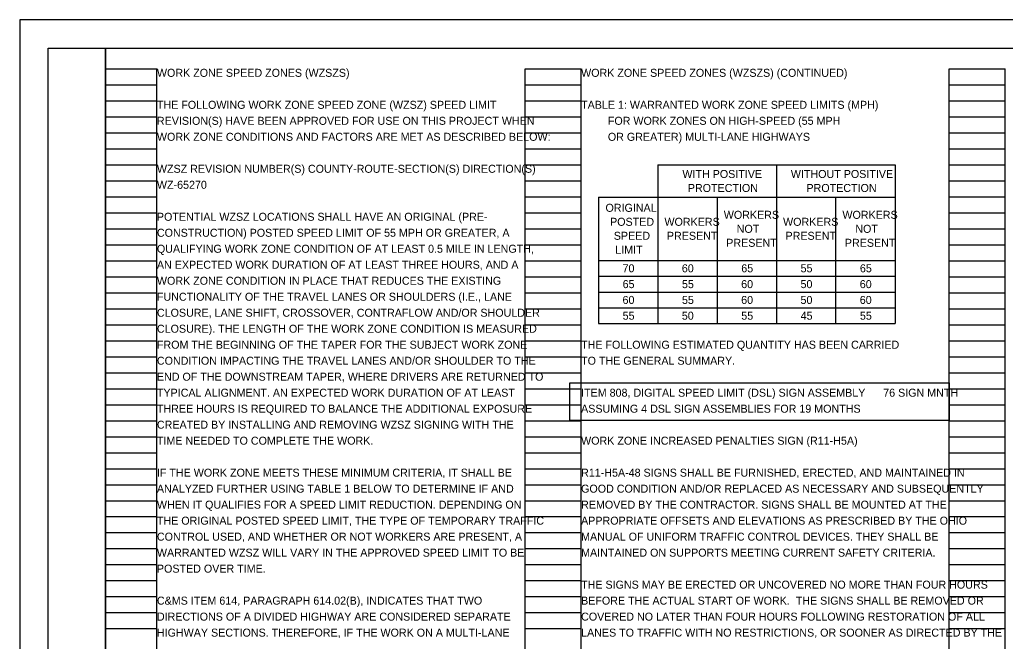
# Model space of a CAD drawing. Extents: x -19 to 34, y 0 to 22.
# Drawn here: x 0 to 17.24, y 11.12 to 22 of the extents above; entities that cross this region are included whole.
import ezdxf

# ---------------------------------------------------------------- set-up
doc = ezdxf.new("R2010")
doc.units = 0
for name, color, linetype in [('SC_Scratch1', 7, 'Continuous'), ('SH_Border', 7, 'Continuous'), ('SH_Cut_Line', 7, 'Continuous'), ('SH_Data', 7, 'Continuous'), ('SH_Text', 7, 'Continuous')]:
    doc.layers.add(name, color=color, linetype=linetype)

msp = doc.modelspace()

# ---------------------------------------------------------------- linework, layer by layer
at = {"layer": 'SC_Scratch1'}
msp.add_lwpolyline([(9.625, 15.64), (16.259, 15.64), (16.259, 14.983), (9.625, 14.983)], close=True, dxfattribs=at)
at = {"layer": 'SH_Border'}
for points in [[(0.5, 21.5), (1.5, 21.5), (1.5, 0.5), (0.5, 0.5)], [(1.5, 21.5), (33.5, 21.5), (33.5, 0.5), (1.5, 0.5)]]:
    msp.add_lwpolyline(points, close=True, dxfattribs=at)
at = {"layer": 'SH_Cut_Line'}
msp.add_lwpolyline([(0, 0), (34, 0), (34, 22), (0, 22)], close=True, dxfattribs=at)
at = {"layer": 'SH_Data'}
for p, q in [((1.5, 0.98), (1.5, 21.14)), ((1.5, 21.14), (2.4, 21.14)), ((2.4, 0.98), (2.4, 21.14)), ((8.84, 0.98), (8.84, 21.14)), ((8.84, 21.14), (9.82, 21.14)), ((9.82, 0.98), (9.82, 21.14)), ((16.26, 0.98), (16.26, 21.14)), ((16.26, 21.14), (17.24, 21.14)), ((17.24, 0.98), (17.24, 21.14)), ((1.5, 20.86), (2.4, 20.86)), ((8.84, 20.86), (9.82, 20.86)), ((16.26, 20.86), (17.24, 20.86)), ((1.5, 20.58), (2.4, 20.58)), ((8.84, 20.58), (9.82, 20.58)), ((16.26, 20.58), (17.24, 20.58)), ((1.5, 20.3), (2.4, 20.3)), ((8.84, 20.3), (9.82, 20.3)), ((16.26, 20.3), (17.24, 20.3)), ((1.5, 20.02), (2.4, 20.02)), ((8.84, 20.02), (9.82, 20.02)), ((16.26, 20.02), (17.24, 20.02)), ((1.5, 19.74), (2.4, 19.74)), ((8.84, 19.74), (9.82, 19.74)), ((16.26, 19.74), (17.24, 19.74)), ((1.5, 19.46), (2.4, 19.46)), ((8.84, 19.46), (9.82, 19.46)), ((16.26, 19.46), (17.24, 19.46)), ((1.5, 19.18), (2.4, 19.18)), ((8.84, 19.18), (9.82, 19.18)), ((16.26, 19.18), (17.24, 19.18)), ((1.5, 18.9), (2.4, 18.9)), ((8.84, 18.9), (9.82, 18.9)), ((16.26, 18.9), (17.24, 18.9)), ((1.5, 18.62), (2.4, 18.62)), ((8.84, 18.62), (9.82, 18.62)), ((16.26, 18.62), (17.24, 18.62)), ((1.5, 18.34), (2.4, 18.34)), ((8.84, 18.34), (9.82, 18.34)), ((16.26, 18.34), (17.24, 18.34)), ((1.5, 18.06), (2.4, 18.06)), ((8.84, 18.06), (9.82, 18.06)), ((16.26, 18.06), (17.24, 18.06)), ((1.5, 17.78), (2.4, 17.78)), ((8.84, 17.78), (9.82, 17.78)), ((16.26, 17.78), (17.24, 17.78)), ((1.5, 17.5), (2.4, 17.5)), ((8.84, 17.5), (9.82, 17.5)), ((16.26, 17.5), (17.24, 17.5)), ((1.5, 17.22), (2.4, 17.22)), ((8.84, 17.22), (9.82, 17.22)), ((16.26, 17.22), (17.24, 17.22)), ((1.5, 16.94), (2.4, 16.94)), ((8.84, 16.94), (9.82, 16.94)), ((16.26, 16.94), (17.24, 16.94)), ((1.5, 16.66), (2.4, 16.66)), ((8.84, 16.66), (9.82, 16.66)), ((16.26, 16.66), (17.24, 16.66)), ((1.5, 16.38), (2.4, 16.38)), ((8.84, 16.38), (9.82, 16.38)), ((16.26, 16.38), (17.24, 16.38)), ((1.5, 16.1), (2.4, 16.1)), ((8.84, 16.1), (9.82, 16.1)), ((16.26, 16.1), (17.24, 16.1)), ((1.5, 15.82), (2.4, 15.82)), ((8.84, 15.82), (9.82, 15.82)), ((16.26, 15.82), (17.24, 15.82)), ((1.5, 15.54), (2.4, 15.54)), ((8.84, 15.54), (9.82, 15.54)), ((16.26, 15.54), (17.24, 15.54)), ((1.5, 15.26), (2.4, 15.26)), ((8.84, 15.26), (9.82, 15.26)), ((16.26, 15.26), (17.24, 15.26)), ((1.5, 14.98), (2.4, 14.98)), ((8.84, 14.98), (9.82, 14.98)), ((16.26, 14.98), (17.24, 14.98)), ((1.5, 14.7), (2.4, 14.7)), ((8.84, 14.7), (9.82, 14.7)), ((16.26, 14.7), (17.24, 14.7)), ((1.5, 14.42), (2.4, 14.42)), ((8.84, 14.42), (9.82, 14.42)), ((16.26, 14.42), (17.24, 14.42)), ((1.5, 14.14), (2.4, 14.14)), ((8.84, 14.14), (9.82, 14.14)), ((16.26, 14.14), (17.24, 14.14)), ((1.5, 13.86), (2.4, 13.86)), ((8.84, 13.86), (9.82, 13.86)), ((16.26, 13.86), (17.24, 13.86)), ((1.5, 13.58), (2.4, 13.58)), ((8.84, 13.58), (9.82, 13.58)), ((16.26, 13.58), (17.24, 13.58)), ((1.5, 13.3), (2.4, 13.3)), ((8.84, 13.3), (9.82, 13.3)), ((16.26, 13.3), (17.24, 13.3)), ((1.5, 13.02), (2.4, 13.02)), ((8.84, 13.02), (9.82, 13.02)), ((16.26, 13.02), (17.24, 13.02)), ((1.5, 12.74), (2.4, 12.74)), ((8.84, 12.74), (9.82, 12.74)), ((16.26, 12.74), (17.24, 12.74)), ((1.5, 12.46), (2.4, 12.46)), ((8.84, 12.46), (9.82, 12.46)), ((16.26, 12.46), (17.24, 12.46)), ((1.5, 12.18), (2.4, 12.18)), ((8.84, 12.18), (9.82, 12.18)), ((16.26, 12.18), (17.24, 12.18)), ((1.5, 11.9), (2.4, 11.9)), ((8.84, 11.9), (9.82, 11.9)), ((16.26, 11.9), (17.24, 11.9)), ((1.5, 11.62), (2.4, 11.62)), ((8.84, 11.62), (9.82, 11.62)), ((16.26, 11.62), (17.24, 11.62)), ((1.5, 11.34), (2.4, 11.34)), ((8.84, 11.34), (9.82, 11.34)), ((16.26, 11.34), (17.24, 11.34))]:
    msp.add_line(p, q, dxfattribs=at)
at = {"layer": 'SH_Text'}
for p, q in [((11.161, 19.46), (15.311, 19.46)), ((11.161, 19.46), (11.161, 16.679)), ((13.236, 19.46), (13.236, 16.679)), ((15.311, 19.46), (15.311, 16.679)), ((10.123, 18.893), (15.311, 18.893)), ((10.123, 18.893), (10.123, 16.679)), ((12.198, 18.893), (12.198, 16.679)), ((14.273, 18.893), (14.273, 16.679)), ((10.123, 17.786), (15.311, 17.786)), ((10.123, 17.509), (15.311, 17.509)), ((10.123, 17.233), (15.311, 17.233)), ((10.123, 16.956), (15.311, 16.956)), ((10.123, 16.679), (15.311, 16.679))]:
    msp.add_line(p, q, dxfattribs=at)

# ---------------------------------------------------------------- texts
for s, p in [('WORK ZONE SPEED ZONES (WZSZS)', (2.4, 21)), ('WORK ZONE SPEED ZONES (WZSZS) (CONTINUED)', (9.82, 21)), ('THE FOLLOWING WORK ZONE SPEED ZONE (WZSZ) SPEED LIMIT ', (2.4, 20.44)), ('TABLE 1: WARRANTED WORK ZONE SPEED LIMITS (MPH)', (9.82, 20.44)), ('REVISION(S) HAVE BEEN APPROVED FOR USE ON THIS PROJECT WHEN ', (2.4, 20.16)), ('         FOR WORK ZONES ON HIGH-SPEED (55 MPH', (9.82, 20.16)), ('WORK ZONE CONDITIONS AND FACTORS ARE MET AS DESCRIBED BELOW: ', (2.4, 19.88)), ('         OR GREATER) MULTI-LANE HIGHWAYS', (9.82, 19.88)), ('WZSZ REVISION NUMBER(S) COUNTY-ROUTE-SECTION(S) DIRECTION(S)', (2.4, 19.32)), ('WITH POSITIVE ', (11.592, 19.229)), ('WITHOUT POSITIVE ', (13.489, 19.229)), ('WZ-65270', (2.4, 19.04)), ('PROTECTION', (11.687, 18.984)), ('PROTECTION', (13.762, 18.984)), ('POTENTIAL WZSZ LOCATIONS SHALL HAVE AN ORIGINAL (PRE-', (2.4, 18.48)), ('ORIGINAL ', (10.247, 18.637)), ('WORKERS ', (12.316, 18.514)), ('WORKERS ', (14.391, 18.514)), ('POSTED ', (10.327, 18.392)), ('WORKERS ', (11.278, 18.392)), ('WORKERS ', (13.353, 18.392)), ('CONSTRUCTION) POSTED SPEED LIMIT OF 55 MPH OR GREATER, A ', (2.4, 18.2)), ('SPEED ', (10.392, 18.147)), ('PRESENT', (11.321, 18.147)), ('NOT ', (12.542, 18.269)), ('PRESENT', (13.396, 18.147)), ('NOT ', (14.617, 18.269)), ('PRESENT', (12.359, 18.024)), ('PRESENT', (14.434, 18.024)), ('QUALIFYING WORK ZONE CONDITION OF AT LEAST 0.5 MILE IN LENGTH, ', (2.4, 17.92)), ('LIMIT', (10.418, 17.902)), ('AN EXPECTED WORK DURATION OF AT LEAST THREE HOURS, AND A ', (2.4, 17.64)), ('70', (10.545, 17.578)), ('60', (11.582, 17.578)), ('65', (12.622, 17.578)), ('55', (13.66, 17.578)), ('65', (14.697, 17.578)), ('WORK ZONE CONDITION IN PLACE THAT REDUCES THE EXISTING ', (2.4, 17.36)), ('65', (10.547, 17.301)), ('55', (11.585, 17.301)), ('60', (12.62, 17.301)), ('50', (13.658, 17.301)), ('60', (14.695, 17.301)), ('FUNCTIONALITY OF THE TRAVEL LANES OR SHOULDERS (I.E., LANE ', (2.4, 17.08)), ('60', (10.545, 17.024)), ('55', (11.585, 17.024)), ('60', (12.62, 17.024)), ('50', (13.658, 17.024)), ('60', (14.695, 17.024)), ('CLOSURE, LANE SHIFT, CROSSOVER, CONTRAFLOW AND/OR SHOULDER ', (2.4, 16.8)), ('55', (10.547, 16.748)), ('50', (11.582, 16.748)), ('55', (12.622, 16.748)), ('45', (13.66, 16.748)), ('55', (14.697, 16.748)), ('CLOSURE). THE LENGTH OF THE WORK ZONE CONDITION IS MEASURED ', (2.4, 16.52)), ('FROM THE BEGINNING OF THE TAPER FOR THE SUBJECT WORK ZONE ', (2.4, 16.24)), ('THE FOLLOWING ESTIMATED QUANTITY HAS BEEN CARRIED', (9.82, 16.24)), ('CONDITION IMPACTING THE TRAVEL LANES AND/OR SHOULDER TO THE ', (2.4, 15.96)), ('TO THE GENERAL SUMMARY.', (9.82, 15.96)), ('END OF THE DOWNSTREAM TAPER, WHERE DRIVERS ARE RETURNED TO ', (2.4, 15.68)), ('TYPICAL ALIGNMENT. AN EXPECTED WORK DURATION OF AT LEAST ', (2.4, 15.4)), ('ITEM 808, DIGITAL SPEED LIMIT (DSL) SIGN ASSEMBLY      76 SIGN MNTH', (9.82, 15.4)), ('THREE HOURS IS REQUIRED TO BALANCE THE ADDITIONAL EXPOSURE ', (2.4, 15.12)), ('ASSUMING 4 DSL SIGN ASSEMBLIES FOR 19 MONTHS', (9.82, 15.12)), ('CREATED BY INSTALLING AND REMOVING WZSZ SIGNING WITH THE ', (2.4, 14.84)), ('TIME NEEDED TO COMPLETE THE WORK.  ', (2.4, 14.56)), ('WORK ZONE INCREASED PENALTIES SIGN (R11-H5A)', (9.82, 14.56)), ('IF THE WORK ZONE MEETS THESE MINIMUM CRITERIA, IT SHALL BE ', (2.4, 14)), ('R11-H5A-48 SIGNS SHALL BE FURNISHED, ERECTED, AND MAINTAINED IN ', (9.82, 14)), ('ANALYZED FURTHER USING TABLE 1 BELOW TO DETERMINE IF AND ', (2.4, 13.72)), ('GOOD CONDITION AND/OR REPLACED AS NECESSARY AND SUBSEQUENTLY ', (9.82, 13.72)), ('WHEN IT QUALIFIES FOR A SPEED LIMIT REDUCTION. DEPENDING ON ', (2.4, 13.44)), ('REMOVED BY THE CONTRACTOR. SIGNS SHALL BE MOUNTED AT THE ', (9.82, 13.44)), ('THE ORIGINAL POSTED SPEED LIMIT, THE TYPE OF TEMPORARY TRAFFIC ', (2.4, 13.16)), ('APPROPRIATE OFFSETS AND ELEVATIONS AS PRESCRIBED BY THE OHIO ', (9.82, 13.16)), ('CONTROL USED, AND WHETHER OR NOT WORKERS ARE PRESENT, A ', (2.4, 12.88)), ('MANUAL OF UNIFORM TRAFFIC CONTROL DEVICES. THEY SHALL BE ', (9.82, 12.88)), ('WARRANTED WZSZ WILL VARY IN THE APPROVED SPEED LIMIT TO BE ', (2.4, 12.6)), ('MAINTAINED ON SUPPORTS MEETING CURRENT SAFETY CRITERIA.', (9.82, 12.6)), ('POSTED OVER TIME. ', (2.4, 12.32)), ('THE SIGNS MAY BE ERECTED OR UNCOVERED NO MORE THAN FOUR HOURS ', (9.82, 12.04)), ('C&MS ITEM 614, PARAGRAPH 614.02(B), INDICATES THAT TWO ', (2.4, 11.76)), ('BEFORE THE ACTUAL START OF WORK.  THE SIGNS SHALL BE REMOVED OR ', (9.82, 11.76)), ('DIRECTIONS OF A DIVIDED HIGHWAY ARE CONSIDERED SEPARATE ', (2.4, 11.48)), ('COVERED NO LATER THAN FOUR HOURS FOLLOWING RESTORATION OF ALL ', (9.82, 11.48)), ('HIGHWAY SECTIONS. THEREFORE, IF THE WORK ON A MULTI-LANE ', (2.4, 11.2)), ('LANES TO TRAFFIC WITH NO RESTRICTIONS, OR SOONER AS DIRECTED BY THE ', (9.82, 11.2))]:
    msp.add_text(s, height=0.14, dxfattribs=at).set_placement(p)

doc.saveas('drawing.dxf')
